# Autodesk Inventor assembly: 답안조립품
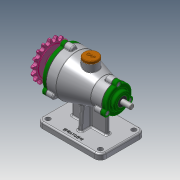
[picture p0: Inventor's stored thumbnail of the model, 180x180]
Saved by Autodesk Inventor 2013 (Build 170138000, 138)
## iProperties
Created: 2020-03
Part Number: 답안조립품
Document SubType Name: Assembly
Designer: user
Author: user
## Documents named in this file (15)
- C:\Users\user\Desktop\700306V1010\답안조립품.iam
- C:\Users\user\Desktop\700306V1010\본체.ipt
- C:\Users\user\Desktop\700306V1010\Ű 4x4x14.ipt
- C:\Users\user\Desktop\700306V1010\개스킷 A.ipt
- C:\Users\user\Desktop\700306V1010\개스킷 B.ipt
- C:\Users\user\Desktop\700306V1010\뒤커버.ipt
- C:\Users\user\Desktop\700306V1010\마개.ipt
- C:\Users\user\Desktop\700306V1010\베어링 6200.ipt
- C:\Users\user\Desktop\700306V1010\베어링 6203.ipt
- C:\Users\user\Desktop\700306V1010\볼트 M5.ipt
- C:\Users\user\Desktop\700306V1010\스프로킷.ipt
- C:\Users\user\Desktop\700306V1010\앞커버.ipt
- C:\Users\user\Desktop\700306V1010\오일 실 10 20 7.ipt
- C:\Users\user\Desktop\700306V1010\오일 실 17 30 8.ipt
- C:\Users\user\Desktop\700306V1010\축.ipt
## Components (3 placed, 3 different names)
1. Ű 4x4x14:1
2. 개스킷 A:1
3. 개스킷 B:1
